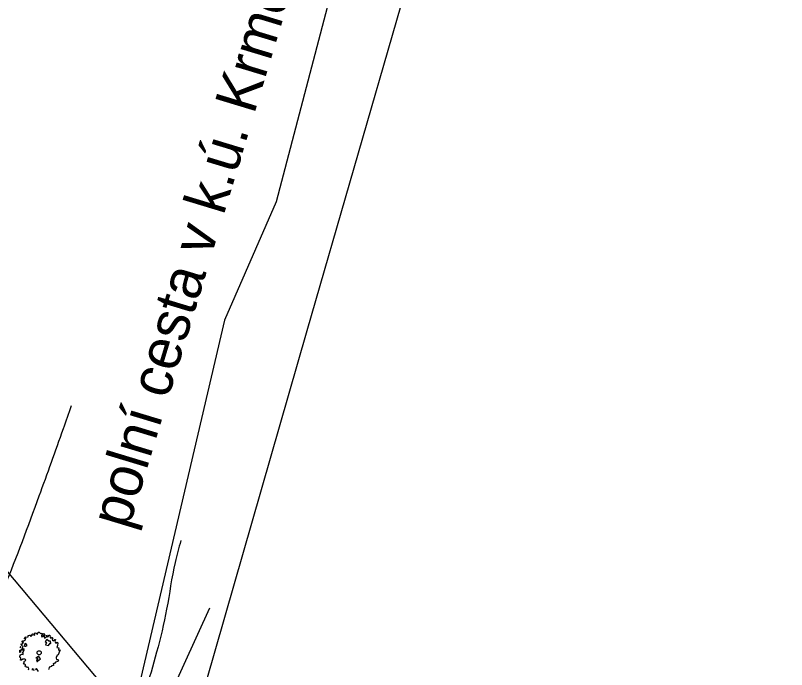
# Model space of a CAD drawing. Extents: x -475575 to -473225, y -1116053 to -1114104.
# Drawn here: x -474334.3 to -474241.7, y -1114439 to -1114360.5 of the extents above; entities that cross this region are included whole.
import ezdxf

# ---------------------------------------------------------------- set-up
doc = ezdxf.new("R2010")
doc.units = 0
for name, color, linetype in [('Implicitní', 7, 'Continuous'), ('IP', 7, 'Continuous'), ('TP_HS', 7, 'Continuous'), ('Vrstevnice_hlavni', 7, 'Continuous'), ('Vrstevnice_vedlejsi', 7, 'Continuous'), ('Vrstva 10', 7, 'Continuous'), ('Vrstva_10', 7, 'Continuous')]:
    doc.layers.add(name, color=color, linetype=linetype)

msp = doc.modelspace()

# ---------------------------------------------------------------- linework, layer by layer
at = {"layer": 'Implicitní'}
msp.add_lwpolyline([(-474392.24, -1114354.32), (-474385.18, -1114363.49), (-474350.25, -1114409.55), (-474320.41, -1114444.98), (-474314.65, -1114451.82), (-474310.64, -1114456.39), (-474234.21, -1114527.12), (-474221.34, -1114539.99), (-474214.34, -1114543), (-474154.82, -1114540.65), (-474095.35, -1114551.68), (-474072.2, -1114553.97), (-474025.99, -1114569.87)], dxfattribs=at)
at = {"layer": 'IP'}
for points in [[(-474332.748, -1114439.059), (-474332.711, -1114438.953), (-474332.741, -1114438.776), (-474332.882, -1114438.741), (-474332.966, -1114438.766), (-474333.065, -1114438.614), (-474333.156, -1114438.662), (-474333.127, -1114438.454), (-474333.186, -1114438.366), (-474333.289, -1114438.378), (-474333.344, -1114438.247), (-474333.275, -1114438.228), (-474333.287, -1114438.147), (-474333.267, -1114438.058), (-474333.231, -1114438.021), (-474333.166, -1114438.002), (-474333.11, -1114437.955), (-474333.072, -1114437.898), (-474333.102, -1114437.817), (-474333.204, -1114437.788), (-474333.424, -1114437.802), (-474333.588, -1114437.888), (-474333.693, -1114437.887), (-474333.676, -1114437.703), (-474333.729, -1114437.576), (-474333.81, -1114437.551), (-474333.768, -1114437.275), (-474333.702, -1114437.247), (-474333.611, -1114437.179), (-474333.41, -1114437.22), (-474333.41, -1114437.121), (-474333.508, -1114436.972), (-474333.357, -1114436.863), (-474333.26, -1114436.69), (-474333.317, -1114436.491), (-474333.521, -1114436.761), (-474333.543, -1114436.626), (-474333.394, -1114436.237), (-474333.534, -1114436.165), (-474333.646, -1114436.004), (-474333.629, -1114435.957), (-474333.522, -1114435.998), (-474333.334, -1114435.776), (-474333.384, -1114435.683), (-474333.539, -1114435.732), (-474333.436, -1114435.575), (-474333.305, -1114435.6), (-474333.136, -1114435.497), (-474333.055, -1114435.281), (-474333.221, -1114435.36), (-474333.25, -1114435.283), (-474333.07, -1114435.09), (-474333.079, -1114435.126), (-474332.783, -1114435.119), (-474332.775, -1114434.936), (-474332.649, -1114434.888), (-474332.53, -1114434.902), (-474332.498, -1114435.004), (-474332.425, -1114435.028), (-474332.284, -1114434.867), (-474332.409, -1114434.854), (-474332.273, -1114434.751), (-474332.137, -1114434.778), (-474332.076, -1114434.927), (-474331.985, -1114434.874), (-474332.041, -1114434.684), (-474331.952, -1114434.623), (-474331.812, -1114434.672), (-474331.69, -1114434.781), (-474331.577, -1114434.56), (-474331.455, -1114434.556), (-474331.315, -1114434.688), (-474331.162, -1114434.662), (-474331.13, -1114434.768), (-474331.208, -1114434.965), (-474331.149, -1114435.106), (-474330.992, -1114435.07), (-474330.918, -1114434.928), (-474331.001, -1114434.945), (-474331.043, -1114434.88), (-474331.068, -1114434.791), (-474330.92, -1114434.708), (-474330.827, -1114434.766), (-474330.841, -1114434.993), (-474330.886, -1114435.074), (-474330.845, -1114435.263), (-474330.839, -1114435.243), (-474330.6, -1114435.085), (-474330.591, -1114434.92), (-474330.455, -1114435.099), (-474330.337, -1114435.053), (-474330.291, -1114434.916), (-474330.193, -1114434.912), (-474330.153, -1114435.236), (-474329.994, -1114435.231), (-474329.923, -1114435.136), (-474329.818, -1114435.291), (-474329.914, -1114435.367), (-474329.872, -1114435.501), (-474329.743, -1114435.573), (-474329.606, -1114435.421), (-474329.519, -1114435.413), (-474329.53, -1114435.55), (-474329.571, -1114435.623), (-474329.557, -1114435.743), (-474329.466, -1114435.844), (-474329.313, -1114435.757), (-474329.248, -1114435.817), (-474329.259, -1114436.129), (-474329.364, -1114436.366), (-474329.09, -1114436.406), (-474329.13, -1114436.618), (-474329.103, -1114436.763), (-474328.942, -1114436.658), (-474329.199, -1114437.255), (-474329.356, -1114437.336), (-474329.353, -1114437.465), (-474329.426, -1114437.498), (-474329.416, -1114437.678), (-474329.38, -1114437.813), (-474329.221, -1114437.831), (-474329.145, -1114437.913), (-474329.214, -1114438.074), (-474329.495, -1114438.126), (-474329.681, -1114438.348), (-474329.797, -1114438.296), (-474329.735, -1114438.537), (-474329.978, -1114438.571), (-474329.999, -1114438.661), (-474330.218, -1114438.74), (-474330.271, -1114438.743), (-474330.317, -1114438.978), (-474330.274, -1114439.041)], [(-474332.108, -1114439.141), (-474332.076, -1114439.029), (-474332.294, -1114438.942), (-474332.33, -1114438.935), (-474332.321, -1114439.089)], [(-474331.562, -1114439.277), (-474331.713, -1114439.029), (-474331.834, -1114438.94), (-474331.927, -1114438.964), (-474331.843, -1114439.056)]]:
    msp.add_lwpolyline(points, dxfattribs=at)
for points in [[(-474330.696, -1114436.053), (-474330.361, -1114436.143), (-474330.139, -1114435.866), (-474330.082, -1114435.911), (-474330.096, -1114435.622), (-474330.316, -1114435.632), (-474330.552, -1114435.44), (-474330.744, -1114435.676), (-474330.564, -1114435.822), (-474330.654, -1114435.933)], [(-474333.748, -1114436.421), (-474333.675, -1114436.34), (-474333.716, -1114436.295), (-474333.749, -1114436.321)], [(-474333.214, -1114436.226), (-474333.056, -1114436.242), (-474332.912, -1114436.154), (-474332.973, -1114436.02), (-474333.084, -1114435.918), (-474333.213, -1114436.041)], [(-474333.744, -1114436.948), (-474333.644, -1114436.763), (-474333.638, -1114436.647), (-474333.786, -1114436.732), (-474333.812, -1114436.702), (-474333.83, -1114436.951)], [(-474331.651, -1114437.894), (-474331.508, -1114437.884), (-474331.316, -1114437.741), (-474331.423, -1114437.597), (-474331.607, -1114437.482), (-474331.858, -1114437.623), (-474331.68, -1114437.641), (-474331.69, -1114437.745), (-474331.753, -1114437.845), (-474331.781, -1114437.889), (-474331.745, -1114438.075), (-474331.652, -1114438.057), (-474331.579, -1114438.001), (-474331.614, -1114437.931)]]:
    msp.add_lwpolyline(points, close=True, dxfattribs=at)
msp.add_circle((-474331.473, -1114437.017), 0.247, dxfattribs=at)
at = {"layer": 'Vrstevnice_hlavni'}
msp.add_spline([(-474314.465, -1114423.562), (-474315.15, -1114426.169), (-474316.163, -1114431.774), (-474317.369, -1114436.945), (-474318.766, -1114441.68), (-474320.354, -1114445.981), (-474321.972, -1114449.681), (-474323.617, -1114452.78), (-474325.291, -1114455.277), (-474326.741, -1114457.93), (-474327.967, -1114460.736), (-474328.969, -1114463.698), (-474329.844, -1114466.14), (-474330.593, -1114468.063), (-474331.215, -1114469.466), (-474332.084, -1114471.237), (-474333.198, -1114473.375), (-474334.559, -1114475.88), (-474336.125, -1114478.272), (-474337.896, -1114480.55), (-474339.872, -1114482.714), (-474341.606, -1114484.471), (-474343.097, -1114485.82), (-474344.345, -1114486.761), (-474345.399, -1114487.69), (-474346.258, -1114488.605), (-474346.922, -1114489.508), (-474348.744, -1114492.982), (-474351.724, -1114499.027), (-474355.862, -1114507.643), (-474358.802, -1114513.52), (-474360.543, -1114516.658), (-474361.086, -1114517.057), (-474361.549, -1114517.367), (-474361.932, -1114517.589), (-474362.234, -1114517.723), (-474362.692, -1114518.027), (-474363.306, -1114518.501), (-474364.075, -1114519.145), (-474364.359, -1114519.998), (-474364.157, -1114521.059), (-474363.469, -1114522.329), (-474364.041, -1114525.543), (-474365.872, -1114530.7), (-474368.962, -1114537.801), (-474371.03, -1114542.537), (-474372.077, -1114544.908), (-474372.101, -1114544.915), (-474372.13, -1114544.928), (-474372.164, -1114544.948), (-474372.202, -1114544.975), (-474373.035, -1114545.505), (-474374.661, -1114546.538), (-474377.082, -1114548.074), (-474379.165, -1114549.699), (-474380.91, -1114551.414), (-474382.317, -1114553.219), (-474383.093, -1114555.278), (-474383.239, -1114557.591), (-474382.271, -1114562.728)], degree=3, dxfattribs=at)
at = {"layer": 'Vrstevnice_vedlejsi'}
msp.add_spline([(-474327.641, -1114407.394), (-474328.603, -1114410.163), (-474331.498, -1114418.235), (-474335.644, -1114429.118), (-474339.003, -1114437.261), (-474341.575, -1114442.664), (-474343.361, -1114445.328), (-474344.701, -1114447.548), (-474345.596, -1114449.324), (-474346.047, -1114450.656), (-474347.707, -1114454.61), (-474350.577, -1114461.188), (-474354.656, -1114470.389), (-474357.396, -1114476.561), (-474358.797, -1114479.703), (-474358.858, -1114479.815), (-474358.928, -1114479.922), (-474359.008, -1114480.025), (-474359.096, -1114480.122), (-474359.174, -1114480.201), (-474359.241, -1114480.261), (-474359.297, -1114480.304), (-474359.345, -1114480.345), (-474359.383, -1114480.386), (-474359.413, -1114480.427), (-474359.495, -1114480.583), (-474359.629, -1114480.854), (-474359.814, -1114481.241), (-474361.795, -1114482.862), (-474365.571, -1114485.716), (-474371.143, -1114489.805), (-474375.891, -1114492.988), (-474379.817, -1114495.267), (-474382.92, -1114496.64), (-474386.819, -1114499.089), (-474391.515, -1114502.613), (-474397.008, -1114507.212), (-474401.449, -1114508.322), (-474404.838, -1114505.943), (-474407.175, -1114500.076), (-474409.173, -1114494.493), (-474410.831, -1114489.194), (-474412.149, -1114484.18), (-474412.82, -1114480.198), (-474412.846, -1114477.248), (-474412.226, -1114475.331), (-474411.8, -1114474.019), (-474411.568, -1114473.315), (-474411.531, -1114473.216), (-474411.527, -1114473.077), (-474411.557, -1114472.897), (-474411.62, -1114472.676), (-474411.726, -1114472.437), (-474411.876, -1114472.179), (-474412.069, -1114471.903), (-474414.084, -1114468.235), (-474417.923, -1114461.176), (-474423.583, -1114450.725), (-474427.711, -1114443.268), (-474430.305, -1114438.804), (-474431.366, -1114437.334), (-474432.27, -1114436.107), (-474433.015, -1114435.123), (-474433.603, -1114434.383), (-474434.851, -1114432.753), (-474436.762, -1114430.233)], degree=3, dxfattribs=at)
at = {"layer": 'Vrstva 10'}
msp.add_lwpolyline([(-474320.412, -1114444.978), (-474314.65, -1114451.82), (-474299.295, -1114398.345), (-474282.356, -1114339.747), (-474269.831, -1114316.275), (-474245.148, -1114261.154), (-474252.42, -1114259.83), (-474273.03, -1114302.54), (-474292.982, -1114343.986), (-474295.83, -1114355.43), (-474303.03, -1114382.92), (-474309.23, -1114397.09)], close=True, dxfattribs=at)
at = {"layer": 'Vrstva_10'}
msp.add_lwpolyline([(-474333.027, -1114502.62), (-474332.577, -1114494.663), (-474330.866, -1114487.83), (-474328.997, -1114477.921), (-474326.996, -1114469.3), (-474323.692, -1114459.536), (-474310.981, -1114431.627)], dxfattribs=at)

# ---------------------------------------------------------------- texts
at = {"layer": 'TP_HS'}
msp.add_text('polní cesta v k.ú. Krmelín', height=5, rotation=73.16187, dxfattribs=at).set_placement((-474320.745, -1114422.329))

doc.saveas('drawing.dxf')
